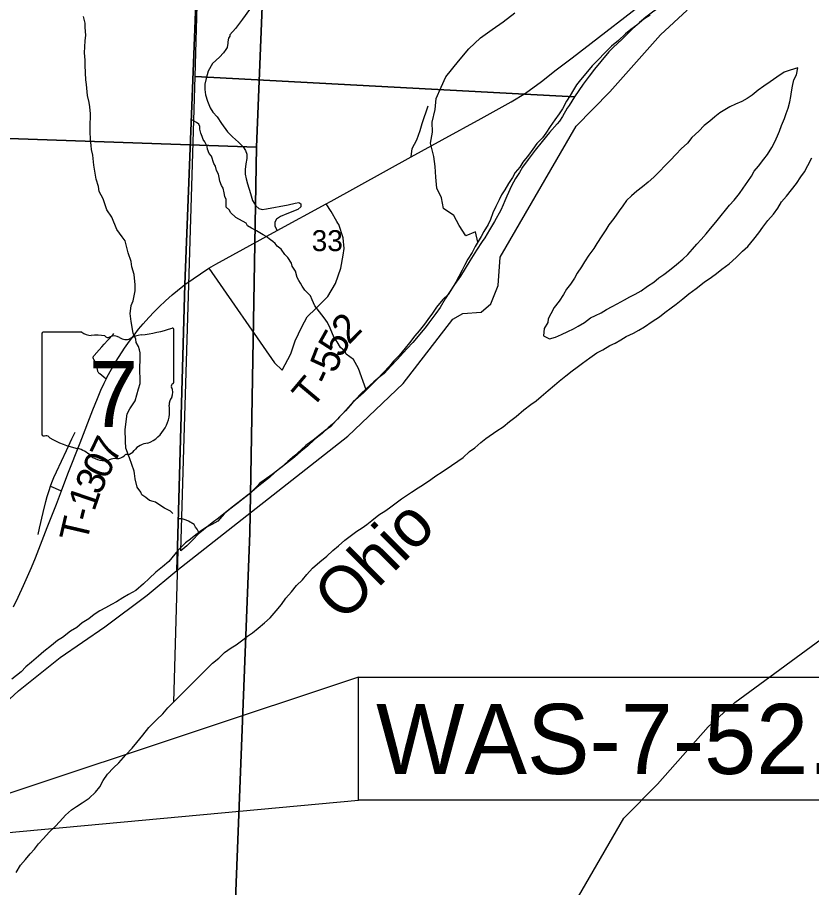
# Model space of a CAD drawing. Extents: x 6.3 to 40.3, y 9 to 31.
# Drawn here: x 12.585 to 14.172, y 26.281 to 28.019 of the extents above; entities that cross this region are included whole.
import ezdxf

# ---------------------------------------------------------------- set-up
doc = ezdxf.new("R2010")
doc.units = 0
for name, color, linetype in [('Default', 7, 'Continuous'), ('GM_X_Major_River', 7, 'Continuous'), ('GM_X_Major_River_Text', 7, 'Continuous'), ('GM_X_Minor_River', 7, 'Continuous'), ('GM_X_Section', 7, 'Continuous'), ('GM_X_Section_Text', 7, 'Continuous'), ('GM_X_State_Location', 7, 'Continuous'), ('GM_X_State_Route', 7, 'Continuous'), ('GM_X_State_Shield', 7, 'Continuous'), ('GM_X_Township_Road', 7, 'Continuous'), ('GM_X_Township_Road_Text', 7, 'Continuous'), ('SH_Cut_Line', 7, 'Continuous'), ('TX_P_1', 7, 'Continuous')]:
    doc.layers.add(name, color=color, linetype=linetype)

msp = doc.modelspace()

# ---------------------------------------------------------------- linework, layer by layer
at = {"layer": 'Default'}
msp.add_lwpolyline([(13.1323, 29.9457), (8.4446, 29.9457), (8.4446, 27.9161), (8.9627, 27.9002), (9.9314, 27.8681), (10.145, 27.8635), (10.7129, 27.8423), (11.7175, 27.8106), (12.5872, 27.7766), (13.0625, 27.76), (13.0974, 28.6191), (13.1136, 29.1637), (13.1156, 29.231), (13.116, 29.2473), (13.13, 29.8856)], close=True, dxfattribs=at)
for points in [[(13.6448, 26.1572), (13.7967, 26.4192), (13.8641, 26.4876), (13.9652, 26.6016), (14.0182, 26.6507), (14.2208, 26.7987), (14.2791, 26.8221), (14.3041, 26.847), (14.4128, 26.9245), (14.4609, 26.9702), (14.6022, 27.1413), (14.809, 27.2988), (14.9021, 27.3498), (15.0488, 27.447), (15.2446, 27.6302), (15.2446, 29.9457)], [(12.5156, 26.6082), (12.5871, 26.6738), (12.6705, 26.7404), (12.7595, 26.8013), (12.8444, 26.8649), (12.9035, 26.9144), (12.9197, 27.4857), (12.9544, 28.3711), (12.9672, 29.1426), (12.4918, 29.1593)], [(13.0974, 28.6191), (13.0625, 27.76), (13.0498, 26.9884), (13.0151, 26.1031)], [(12.9544, 28.3711), (12.9197, 27.4857), (12.9035, 26.9144), (13.245, 27.1825), (13.356, 27.2878), (13.4548, 27.4161), (13.4753, 27.4274), (13.5116, 27.4304), (13.5309, 27.4467), (13.5457, 27.4833), (13.5495, 27.5399), (13.7013, 27.8019), (13.7687, 27.8702), (13.8699, 27.9843), (13.9229, 28.0334)], [(12.5512, 25.1589), (12.6109, 25.2255), (12.6825, 25.2911), (12.7658, 25.3577), (12.8549, 25.4186), (12.9398, 25.4822), (12.9988, 25.5318), (13.0151, 26.1031), (13.0498, 26.9884), (13.0625, 27.76), (12.5872, 27.7766), (11.7175, 27.8106)]]:
    msp.add_lwpolyline(points, dxfattribs=at)
at = {"layer": 'GM_X_Major_River'}
msp.add_line((12.9057, 26.9542), (12.8971, 26.651), dxfattribs=at)
for points in [[(13.8495, 28.0234), (13.8367, 28.0152), (13.8225, 28.0035), (13.8109, 27.9946)], [(13.8109, 27.9946), (13.8001, 27.9861), (13.7863, 27.973), (13.772, 27.9617), (13.759, 27.9482), (13.7456, 27.9343), (13.7333, 27.922), (13.721, 27.907), (13.7098, 27.8939), (13.702, 27.8839), (13.6961, 27.8743), (13.6895, 27.8628), (13.6821, 27.8513), (13.674, 27.8364), (13.6673, 27.826), (13.6588, 27.8141), (13.6492, 27.8007), (13.6411, 27.788), (13.634, 27.7784), (13.6232, 27.7668), (13.6147, 27.7557), (13.6061, 27.7438), (13.595, 27.7296), (13.5887, 27.72), (13.5794, 27.7092), (13.5743, 27.6992), (13.5665, 27.6874), (13.5588, 27.6747), (13.5525, 27.6644), (13.5473, 27.6544), (13.5407, 27.641), (13.5349, 27.6284), (13.5302, 27.6154), (13.5254, 27.6051), (13.5173, 27.5913), (13.5118, 27.5814), (13.5055, 27.571), (13.5, 27.5614), (13.4937, 27.5496), (13.4848, 27.5358), (13.4789, 27.5247), (13.4738, 27.514), (13.4668, 27.5013), (13.4609, 27.4902), (13.4536, 27.478), (13.4458, 27.4657), (13.4354, 27.4553), (13.4227, 27.4403), (13.4142, 27.428), (13.4049, 27.4157), (13.3983, 27.4061), (13.3879, 27.393), (13.3789, 27.3826), (13.3685, 27.3688), (13.3596, 27.3584), (13.3477, 27.3434), (13.3365, 27.3326), (13.3284, 27.3226), (13.3157, 27.3091), (13.3034, 27.2956), (13.29, 27.2825), (13.2766, 27.269), (13.2661, 27.2597), (13.256, 27.2512), (13.2467, 27.2404), (13.2344, 27.227), (13.2221, 27.2135), (13.2113, 27.2019), (13.2001, 27.1938), (13.1903, 27.186), (13.1784, 27.1767), (13.1615, 27.1635), (13.1518, 27.155), (13.1387, 27.1434), (13.1253, 27.1318), (13.113, 27.1206), (13.0991, 27.109), (13.0887, 27.1001), (13.0737, 27.0877), (13.064, 27.0803), (13.0483, 27.0664), (13.0363, 27.0575), (13.0236, 27.0474), (13.0093, 27.0369), (12.9981, 27.0273), (12.9858, 27.0127), (12.9734, 27.006), (12.9629, 27.0005), (12.9532, 26.9939), (12.9416, 26.9854), (12.9307, 26.9765), (12.921, 26.9691), (12.9057, 26.9542)], [(13.6446, 27.4095), (13.6376, 27.3976), (13.6363, 27.3828), (13.6485, 27.3766), (13.6599, 27.3802), (13.6719, 27.3857), (13.6851, 27.3916), (13.696, 27.3967), (13.7057, 27.4022), (13.7178, 27.4096), (13.7301, 27.4189), (13.7399, 27.4236), (13.7512, 27.4291), (13.7621, 27.4354), (13.7733, 27.4413), (13.7831, 27.4467), (13.7978, 27.4546), (13.809, 27.4605), (13.8195, 27.4663), (13.8312, 27.473), (13.8443, 27.4823), (13.8567, 27.4901), (13.8668, 27.4986), (13.8765, 27.5056), (13.8881, 27.5138), (13.9016, 27.5254), (13.9143, 27.5362), (13.9244, 27.5455), (13.9337, 27.5563), (13.9426, 27.5659), (13.9512, 27.5755), (13.9609, 27.5863), (13.9698, 27.5975), (13.9802, 27.6102), (13.9914, 27.6229), (13.9999, 27.6336), (14.0077, 27.6436), (14.017, 27.6536), (14.0278, 27.6675), (14.0348, 27.6775), (14.0441, 27.6913), (14.0515, 27.7016), (14.0574, 27.7116), (14.0655, 27.722), (14.0767, 27.7355), (14.0834, 27.7454), (14.0922, 27.7589), (14.0981, 27.7707), (14.104, 27.7822), (14.108, 27.7918), (14.112, 27.8032), (14.1178, 27.817), (14.1207, 27.8269), (14.1251, 27.8379), (14.1283, 27.8501), (14.1304, 27.8608), (14.1314, 27.8703), (14.1334, 27.8817), (14.1363, 27.8943), (14.1414, 27.9042), (14.1442, 27.9179)], [(14.1442, 27.9179), (14.1288, 27.9135), (14.1171, 27.9095), (14.1024, 27.8998), (14.089, 27.8901), (14.0762, 27.8815), (14.065, 27.8733), (14.053, 27.8637), (14.0429, 27.857), (14.0324, 27.8512), (14.0199, 27.8456), (14.0083, 27.8401), (13.9985, 27.8343), (13.9884, 27.8284), (13.9787, 27.8203), (13.9686, 27.8114), (13.9573, 27.8032), (13.9465, 27.792), (13.9327, 27.7789), (13.9238, 27.7678), (13.9115, 27.7566), (13.9014, 27.7458), (13.8895, 27.7334), (13.8783, 27.7222), (13.8686, 27.7118), (13.8567, 27.6999), (13.8451, 27.6898), (13.8339, 27.6805), (13.8226, 27.672), (13.8118, 27.6627), (13.8021, 27.653), (13.7947, 27.6427), (13.7873, 27.6327), (13.7769, 27.617), (13.7669, 27.6043), (13.761, 27.5947), (13.7528, 27.5824), (13.7428, 27.5671), (13.7366, 27.5571), (13.7265, 27.544), (13.7184, 27.531), (13.7118, 27.521), (13.7033, 27.508), (13.6981, 27.498), (13.6903, 27.4858), (13.6822, 27.4761), (13.6759, 27.4654), (13.6674, 27.4524), (13.6578, 27.4393), (13.6511, 27.4267), (13.6452, 27.4167), (13.6446, 27.4095)], [(13.9149, 27.4566), (13.9268, 27.4666), (13.9414, 27.4775), (13.9571, 27.4899), (13.9718, 27.5), (13.9815, 27.5074), (13.9923, 27.5159), (14.007, 27.5268), (14.0212, 27.5392), (14.0335, 27.5519), (14.0443, 27.5616), (14.0566, 27.5758), (14.0666, 27.5889), (14.0744, 27.6), (14.0844, 27.6131), (14.0955, 27.6261), (14.1045, 27.6377), (14.1118, 27.6507), (14.1219, 27.6619), (14.1319, 27.6742), (14.1416, 27.6869), (14.1501, 27.7003), (14.1579, 27.7103), (14.1641, 27.7229), (14.1722, 27.7382)], [(12.8971, 26.651), (12.975, 26.7292), (12.9877, 26.7393), (12.9989, 26.7501), (13.012, 26.7594), (13.0221, 26.766), (13.0352, 26.7757), (13.045, 26.7831), (13.0547, 26.7897), (13.0663, 26.799), (13.0786, 26.8098), (13.0902, 26.8199), (13.1021, 26.8337), (13.1125, 26.8464), (13.1214, 26.8587), (13.1326, 26.8718), (13.143, 26.8841), (13.1546, 26.8953), (13.1635, 26.9064), (13.175, 26.9188), (13.1896, 26.9315), (13.2031, 26.9428), (13.2154, 26.9544), (13.2266, 26.9636), (13.2393, 26.9745), (13.2528, 26.9846), (13.2633, 26.9927), (13.2738, 26.9993), (13.2835, 27.0059), (13.2933, 27.0137), (13.3075, 27.0253), (13.321, 27.0343), (13.3315, 27.0413), (13.3416, 27.049), (13.3524, 27.0572), (13.3626, 27.0642), (13.3723, 27.0708), (13.3858, 27.0793), (13.3963, 27.086), (13.4109, 27.0957), (13.4214, 27.1031), (13.4338, 27.1109), (13.4525, 27.1241), (13.4649, 27.1326), (13.4758, 27.14), (13.4885, 27.1516), (13.4993, 27.1594), (13.5109, 27.1698), (13.521, 27.178), (13.5428, 27.1931), (13.5559, 27.2013), (13.5682, 27.2118), (13.5813, 27.2215), (13.5967, 27.2354), (13.6109, 27.2459), (13.6214, 27.2532), (13.6315, 27.2614), (13.6457, 27.2738), (13.658, 27.2846), (13.6677, 27.2923), (13.6808, 27.3032), (13.6932, 27.3132), (13.7033, 27.3202), (13.7142, 27.328), (13.7291, 27.3389), (13.743, 27.3486), (13.755, 27.3552), (13.7685, 27.3634), (13.7791, 27.3685), (13.7907, 27.3748), (13.8012, 27.3814), (13.8159, 27.3885), (13.8264, 27.394), (13.8377, 27.4006), (13.8534, 27.4112), (13.8677, 27.4205), (13.8785, 27.4294), (13.8913, 27.4391), (13.9014, 27.4461), (13.9149, 27.4566)], [(12.9057, 26.9542), (12.8879, 26.9323), (12.8749, 26.9214), (12.8614, 26.9105), (12.8484, 26.8982), (12.8368, 26.8873), (12.8215, 26.8745), (12.8072, 26.8663), (12.796, 26.8593), (12.7828, 26.8515), (12.7731, 26.846), (12.761, 26.8393), (12.7498, 26.8334), (12.7385, 26.8264), (12.7277, 26.8174), (12.7142, 26.8096), (12.7037, 26.8003), (12.6913, 26.7933), (12.6753, 26.7805), (12.6655, 26.7742), (12.6535, 26.7641), (12.6382, 26.7521), (12.627, 26.7432), (12.6132, 26.7308), (12.602, 26.7218), (12.5927, 26.7118), (12.574, 26.6974)], [(12.583, 26.3111), (12.5911, 26.3257), (12.6012, 26.3368), (12.6104, 26.348), (12.6194, 26.3577), (12.6275, 26.3681), (12.6376, 26.3789), (12.6487, 26.3912), (12.6607, 26.4028), (12.6696, 26.4128), (12.6811, 26.4252), (12.6934, 26.436), (12.7032, 26.443), (12.7144, 26.45), (12.7287, 26.4594), (12.7414, 26.4714), (12.7495, 26.4822), (12.7565, 26.4944), (12.7654, 26.5071), (12.7769, 26.5198), (12.7877, 26.5299), (12.8018, 26.5461), (12.8141, 26.5596), (12.8238, 26.5704), (12.8357, 26.5854), (12.8479, 26.6004), (12.8635, 26.6166), (12.8759, 26.6278), (12.8859, 26.6398), (12.8971, 26.651)]]:
    msp.add_lwpolyline(points, dxfattribs=at)
at = {"layer": 'GM_X_Minor_River'}
for points in [[(12.8958, 27.0282), (12.8909, 27.0329), (12.8787, 27.0388), (12.8679, 27.0463), (12.8611, 27.0508), (12.8565, 27.0519), (12.8489, 27.0541), (12.842, 27.0597), (12.8336, 27.0653), (12.832, 27.0706), (12.8247, 27.0808), (12.8203, 27.0975), (12.8195, 27.1024), (12.8191, 27.1077), (12.8183, 27.1126), (12.8092, 27.1395), (12.8018, 27.1588), (12.8009, 27.1728), (12.8007, 27.196), (12.8045, 27.2268), (12.8097, 27.2371), (12.8202, 27.2528), (12.8271, 27.2768), (12.8301, 27.2878), (12.8297, 27.3224), (12.8307, 27.3323), (12.8305, 27.3486), (12.829, 27.3547), (12.8274, 27.3619), (12.8227, 27.3694), (12.8219, 27.3762), (12.8165, 27.3883), (12.8124, 27.4118), (12.8103, 27.4274), (12.8118, 27.4377), (12.8125, 27.4434), (12.8162, 27.4525), (12.8201, 27.4727), (12.8207, 27.4849), (12.8182, 27.5057), (12.8135, 27.5209), (12.8123, 27.5311), (12.8064, 27.5489), (12.8005, 27.5728), (12.7947, 27.5807), (12.7835, 27.595), (12.7737, 27.62), (12.7641, 27.6347), (12.7567, 27.6563), (12.7485, 27.671), (12.7473, 27.6809), (12.7422, 27.696), (12.7393, 27.7157), (12.7381, 27.7237), (12.736, 27.7438), (12.7332, 27.7552), (12.7327, 27.7628), (12.7315, 27.7745), (12.7302, 27.792), (12.7305, 27.8), (12.7309, 27.8266), (12.7296, 27.8406), (12.7288, 27.849), (12.7252, 27.8626), (12.7235, 27.8846), (12.7219, 27.8941), (12.7204, 27.9226), (12.7207, 27.9332), (12.7194, 27.948), (12.7207, 27.9723), (12.7217, 27.9837), (12.7208, 27.9989), (12.7203, 28.0073), (12.7175, 28.0206)], [(13.505, 27.5701), (13.5005, 27.5903), (13.4812, 27.5827), (13.468, 27.6035), (13.457, 27.6235), (13.4362, 27.6371), (13.4324, 27.6582), (13.4229, 27.6775), (13.4214, 27.6998), (13.4199, 27.7209), (13.4173, 27.7413), (13.4105, 27.7674), (13.4143, 27.7896), (13.4135, 27.8097), (13.4196, 27.8349), (13.4218, 27.8569), (13.4317, 27.8795), (13.4411, 27.8999), (13.4661, 27.9316), (13.4873, 27.9562), (13.5104, 27.9781), (13.5339, 27.9947), (13.5559, 28.0102), (13.5786, 28.0279)], [(13.2822, 27.2747), (13.2666, 27.3177), (13.2563, 27.3357), (13.242, 27.346), (13.24, 27.3517), (13.2304, 27.3598), (13.224, 27.3711), (13.2178, 27.3789), (13.2102, 27.3981), (13.2046, 27.4094), (13.1983, 27.4188), (13.1796, 27.4427), (13.174, 27.4551), (13.1704, 27.4626), (13.1595, 27.4741), (13.154, 27.482), (13.1505, 27.488), (13.1477, 27.4933), (13.1442, 27.4996), (13.1405, 27.5121), (13.1342, 27.5218), (13.1329, 27.5279), (13.1255, 27.5395), (13.1193, 27.5455), (13.1118, 27.5563), (13.1041, 27.5618), (13.0998, 27.5674), (13.0952, 27.5711), (13.0909, 27.5745), (13.082, 27.5811), (13.0759, 27.5848), (13.0628, 27.5928), (13.0528, 27.5976), (13.0451, 27.6023), (13.0424, 27.608), (13.0216, 27.6193), (13.0108, 27.6289), (13.0088, 27.6338), (13.0022, 27.6397), (13.0024, 27.6458), (13.0019, 27.6549), (12.9994, 27.6613), (12.9982, 27.6682), (12.9964, 27.678), (12.9929, 27.6829), (12.9897, 27.6919), (12.988, 27.6991), (12.9871, 27.7059), (12.9827, 27.713), (12.981, 27.7221), (12.9779, 27.727), (12.973, 27.7417), (12.968, 27.7473), (12.9651, 27.7556), (12.9642, 27.7609), (12.9595, 27.7707), (12.956, 27.7748), (12.9543, 27.7808), (12.9515, 27.7876), (12.9498, 27.7955), (12.9493, 27.8008), (12.9477, 27.8058), (12.9431, 27.8091), (12.9335, 27.8146), (12.9312, 27.8153)], [(12.9478, 26.99), (12.9446, 26.9966), (12.9411, 27.0007), (12.938, 27.006), (12.9272, 27.013), (12.9226, 27.0148), (12.9161, 27.0169), (12.9119, 27.0172), (12.9058, 27.0174)]]:
    msp.add_lwpolyline(points, dxfattribs=at)
at = {"layer": 'GM_X_Section'}
for points in [[(13.9707, 28.8429), (13.9488, 28.0971), (13.9414, 28.0891), (13.9298, 28.0809), (13.9193, 28.0713), (13.9144, 28.0682), (13.9073, 28.0646), (13.887, 28.0511), (13.8713, 28.041), (13.8566, 28.0312), (13.8409, 28.0192), (13.8282, 28.0088), (13.8129, 27.9945), (13.7935, 27.9757), (13.7752, 27.9591), (13.7666, 27.9502), (13.751, 27.931), (13.7384, 27.9153), (13.7272, 27.9015), (13.7153, 27.8854), (13.6983, 27.8601), (12.9402, 27.9008), (12.9478, 28.1619), (12.9705, 28.903)], [(12.9402, 27.9008), (13.6983, 27.8601), (13.6872, 27.8429), (13.6835, 27.8375), (13.6743, 27.821), (13.668, 27.8115), (13.6635, 27.8061), (13.6483, 27.7888), (13.6334, 27.7711), (13.6193, 27.7535), (13.6055, 27.7351), (13.5944, 27.7201), (13.5881, 27.7094), (13.5804, 27.6971), (13.5723, 27.6826), (13.5631, 27.662), (13.5587, 27.6525), (13.5554, 27.6448), (13.5511, 27.6341), (13.5382, 27.6112), (13.5286, 27.5948), (13.519, 27.5787), (13.5134, 27.571), (13.5023, 27.5538), (13.489, 27.5324), (13.4702, 27.5021), (13.4587, 27.4856), (13.4483, 27.4703), (13.4398, 27.4565), (13.4299, 27.4397), (13.4213, 27.4278), (13.4069, 27.409), (13.3998, 27.3987), (13.3953, 27.3937), (13.3857, 27.3822), (13.3753, 27.3695), (13.3637, 27.3575), (13.3566, 27.3495), (13.3436, 27.3356), (13.3309, 27.3222), (13.3179, 27.3079), (13.31, 27.3014), (13.2973, 27.2913), (13.2898, 27.2844), (13.2827, 27.2778), (13.2704, 27.2662), (13.2544, 27.2489), (13.2403, 27.2328), (13.2287, 27.2212), (13.2246, 27.2166), (13.2145, 27.2062), (13.2063, 27.1989), (13.194, 27.1881), (13.179, 27.1757), (13.1656, 27.163), (13.1517, 27.1518), (13.1387, 27.1402), (13.127, 27.1313), (13.1113, 27.1193), (13.0941, 27.1058), (13.0784, 27.0949), (13.0697, 27.0887), (13.0634, 27.0822), (13.0563, 27.0749), (13.0466, 27.066), (13.0316, 27.054), (13.0144, 27.0405), (12.9867, 27.0184), (12.974, 27.0091), (12.9568, 26.9956), (12.9463, 26.9867), (12.9362, 26.9759), (12.9236, 26.9636), (12.9119, 26.9536), (12.9176, 27.1566)]]:
    msp.add_lwpolyline(points, close=True, dxfattribs=at)
at = {"layer": 'GM_X_State_Route'}
for points in [[(13.6618, 27.914), (13.6933, 27.9379), (13.8662, 28.0723)], [(13.212, 27.652), (13.372, 27.7402), (13.4338, 27.7744), (13.5117, 27.8167), (13.5713, 27.8503), (13.6005, 27.8674), (13.6319, 27.8912), (13.6618, 27.914)], [(12.9199, 27.4852), (12.9679, 27.5178), (12.9818, 27.5261), (13.1044, 27.5936), (13.202, 27.6465), (13.212, 27.652)], [(12.5773, 26.8417), (12.5865, 26.8607), (12.5974, 26.8844), (12.6132, 26.9202), (12.6214, 26.9397), (12.6314, 26.9651), (12.6447, 26.9999), (12.6633, 27.0467), (12.6733, 27.0731), (12.6862, 27.1071), (12.7106, 27.169), (12.7359, 27.2352), (12.745, 27.2577), (12.752, 27.2743), (12.7585, 27.2884), (12.7626, 27.2966), (12.7646, 27.3007), (12.7732, 27.3165), (12.7814, 27.3305), (12.7883, 27.3416), (12.7993, 27.3582), (12.8093, 27.3725), (12.8182, 27.3845), (12.8274, 27.3962), (12.8362, 27.4067), (12.8475, 27.4192), (12.8582, 27.4305), (12.8684, 27.4405), (12.8811, 27.4525), (12.8945, 27.4646), (12.9049, 27.4735), (12.9156, 27.482), (12.9199, 27.4852)]]:
    msp.add_lwpolyline(points, dxfattribs=at)
at = {"layer": 'GM_X_State_Shield'}
for p, q in [((12.8977, 27.2904), (12.8977, 27.3951)), ((12.634, 27.3867), (12.634, 27.1866)), ((12.7138, 27.3901), (12.6366, 27.3901)), ((12.8977, 27.2904), (12.8977, 27.2904))]:
    msp.add_line(p, q, dxfattribs=at)
for centre, radius, start, end in [((12.8038, 27.663), 0.2796, 275.8445, 288.9065), ((12.8948, 27.3955), 0.00294, 351.8621, 97.738), ((12.637, 27.3871), 0.00305, 98.1301, 188.1301), ((12.7322, 27.4134), 0.0296, 231.6195, 271.1119), ((12.742, 27.2778), 0.1064, 80.4867, 94.9883), ((12.7662, 27.3882), 0.00855, 219.7921, 297.1024), ((12.7787, 27.365), 0.0178, 54.4667, 119.1411), ((12.8017, 27.3968), 0.0214, 233.8562, 294.8282), ((12.8394, 27.329), 0.0563, 97.3462, 120.7689), ((12.8946, 27.29), 0.00314, 289.6038, 7.7341), ((12.897, 27.2827), 0.00454, 107.944, 210.337), ((12.8681, 27.2695), 0.0273, 340.033, 23.6496), ((12.9082, 27.2466), 0.0198, 136.8065, 186.9296), ((12.8194, 27.2333), 0.0699, 292.3089, 8.9858), ((12.6371, 27.1861), 0.00308, 171.9584, 258.3066), ((12.6375, 27.2066), 0.0235, 267.339, 280.6039), ((12.6423, 27.175), 0.00848, 29.7484, 93.2717), ((12.7494, 27.3548), 0.2019, 240.4129, 257.1985), ((12.8489, 27.1304), 0.0383, 94.4031, 142.5768), ((12.6892, 27.0967), 0.0632, 47.1842, 75.836), ((12.8004, 27.1672), 0.0226, 282.8732, 323.2771), ((12.7575, 27.174), 0.0401, 230.7004, 286.2918), ((12.7807, 27.1048), 0.0329, 85.6951, 111.2099), ((12.7836, 27.1591), 0.0214, 268.777, 315.5493), ((12.803, 27.1397), 0.00601, 65.7517, 132.6484)]:
    msp.add_arc(centre, radius, start, end, dxfattribs=at)
at = {"layer": 'GM_X_Township_Road'}
for points in [[(13.0489, 28.0347), (13.0349, 28.0151), (13.0209, 27.9969), (13.0097, 27.9843), (13.0097, 27.9815), (13.0069, 27.9773), (13.0055, 27.9703), (13.0055, 27.9675), (13.0041, 27.9591), (13.0013, 27.9549), (12.9971, 27.9479), (12.9887, 27.9395), (12.9747, 27.9269), (12.966, 27.9115), (12.9623, 27.8972), (12.9596, 27.8856), (12.9596, 27.8748), (12.9609, 27.8641), (12.9649, 27.8516), (12.9704, 27.8386), (12.9756, 27.8299), (12.9842, 27.82), (12.993, 27.8068), (13.0048, 27.7904), (13.0149, 27.7801), (13.0267, 27.7698), (13.0362, 27.7601), (13.041, 27.7531), (13.0434, 27.7456), (13.0432, 27.7369), (13.0417, 27.7261), (13.0403, 27.7154), (13.0403, 27.7057), (13.0423, 27.6967), (13.0449, 27.6862), (13.0509, 27.6669), (13.0548, 27.6535), (13.0612, 27.6423), (13.0673, 27.6373), (13.0743, 27.6355), (13.0831, 27.6366), (13.1263, 27.6443), (13.1399, 27.648), (13.1476, 27.6494), (13.1511, 27.6465), (13.1511, 27.6408), (13.1456, 27.6355), (13.1237, 27.6263), (13.1107, 27.6213), (13.1028, 27.616), (13.0996, 27.6099), (13.0993, 27.6022), (13.1044, 27.5936)], [(13.372, 27.7402), (13.3737, 27.7568), (13.3829, 27.7744), (13.3899, 27.7928), (13.3935, 27.8071), (13.4057, 27.8424)], [(13.2234, 27.6113), (13.2119, 27.631), (13.202, 27.6465)], [(12.9679, 27.5178), (13.0987, 27.3291), (13.1143, 27.3141), (13.1316, 27.3467), (13.1403, 27.3727), (13.1534, 27.4009), (13.1642, 27.4205), (13.1816, 27.4378), (13.2054, 27.4617), (13.2206, 27.4877), (13.2315, 27.5181), (13.2358, 27.5442), (13.238, 27.5572), (13.2358, 27.5789), (13.2271, 27.605), (13.2255, 27.6078), (13.2234, 27.6113)], [(12.7626, 27.2966), (12.7581, 27.3001), (12.7499, 27.3067), (12.749, 27.3076), (12.7481, 27.3086), (12.7473, 27.3096), (12.7466, 27.3106), (12.746, 27.3117), (12.7456, 27.3128), (12.7452, 27.3141), (12.745, 27.3152), (12.7438, 27.3238), (12.7434, 27.3254), (12.7429, 27.3268), (12.7423, 27.3282), (12.7417, 27.3296), (12.7401, 27.3323), (12.7377, 27.3359), (12.7373, 27.3367), (12.737, 27.3376), (12.7368, 27.3383), (12.7366, 27.3391), (12.7367, 27.3399), (12.7368, 27.3406), (12.7373, 27.3418), (12.738, 27.3428), (12.7387, 27.3438), (12.7487, 27.3548), (12.7539, 27.3609), (12.7584, 27.366), (12.7655, 27.3739), (12.7764, 27.3858), (12.778, 27.3877)], [(12.6515, 27.0826), (12.654, 27.0897), (12.6581, 27.1001), (12.6631, 27.1115), (12.683, 27.1537), (12.6941, 27.1773), (12.7006, 27.1907)], [(12.6269, 26.9863), (12.6295, 26.9985), (12.6369, 27.03), (12.642, 27.0518), (12.6447, 27.062), (12.6484, 27.0739), (12.6515, 27.0826)], [(12.6515, 27.0826), (12.6559, 27.0806), (12.6605, 27.0785), (12.668, 27.0753), (12.6733, 27.0731)]]:
    msp.add_lwpolyline(points, dxfattribs=at)
at = {"layer": 'SH_Cut_Line'}
for points in [[(12.5156, 26.6082), (12.5871, 26.6738), (12.6705, 26.7404), (12.7595, 26.8013), (12.8444, 26.8649), (12.9035, 26.9144), (12.9197, 27.4857), (12.9544, 28.3711), (12.9672, 29.1426), (12.4918, 29.1593)], [(12.9544, 28.3711), (12.9197, 27.4857), (12.9035, 26.9144), (13.245, 27.1825), (13.356, 27.2878), (13.4548, 27.4161), (13.4753, 27.4274), (13.5116, 27.4304), (13.5309, 27.4467), (13.5457, 27.4833), (13.5495, 27.5399), (13.7013, 27.8019), (13.7687, 27.8702), (13.8699, 27.9843), (13.9229, 28.0334)]]:
    msp.add_lwpolyline(points, dxfattribs=at)
at = {"layer": 'TX_P_1'}
for points in [[(13.2665, 26.7014), (12.2432, 26.3609), (13.2665, 26.4555)], [(13.2665, 26.7014), (14.523, 26.7014), (14.523, 26.4555), (13.2665, 26.4555)]]:
    msp.add_lwpolyline(points, close=True, dxfattribs=at)

# ---------------------------------------------------------------- texts
at = {"layer": 'GM_X_Major_River_Text'}
msp.add_text('Ohio', height=0.09469, rotation=45.0009, dxfattribs=at).set_placement((13.2357, 26.8085))
at = {"layer": 'GM_X_Section_Text'}
msp.add_text('33', height=0.04186, rotation=0, dxfattribs=at).set_placement((13.1731, 27.5521))
at = {"layer": 'GM_X_State_Location'}
for s in ['s', 'r']:
    msp.add_text(s, height=0.000189, dxfattribs=at).set_placement((12.7629, 27.2733))
msp.add_text('7', height=0.000189, rotation=0, dxfattribs=at).set_placement((12.7344, 27.2596))
at = {"layer": 'GM_X_State_Shield'}
msp.add_text('7', height=0.1318, dxfattribs=at).set_placement((12.7281, 27.2007))
at = {"layer": 'GM_X_Township_Road_Text'}
for s, rotation, p in [('2', 45.2612, (13.2473, 27.3641)), ('5', 60.5992, (13.2325, 27.3368)), ('5', 68.6599, (13.2207, 27.3061)), ('-', 64.4755, (13.2088, 27.2809)), ('T', 49.9653, (13.173, 27.2352)), ('7', 64.2565, (12.7789, 27.1255)), ('0', 64.5114, (12.7638, 27.094)), ('3', 65.7955, (12.7496, 27.0624)), ('1', 71.1569, (12.7388, 27.0306)), ('-', 75.7082, (12.7334, 27.0091)), ('T', 76.839, (12.7238, 26.968))]:
    msp.add_text(s, height=0.0568, rotation=rotation, dxfattribs=at).set_placement(p)
at = {"layer": 'TX_P_1'}
msp.add_text('WAS-7-52.79', height=0.14, dxfattribs=at).set_placement((13.3017, 26.5077))

doc.saveas('drawing.dxf')
